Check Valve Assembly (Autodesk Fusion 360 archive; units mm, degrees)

design "Check Valve Assembly" references "PC012-406-7000-SST-0810-C-N-IN", "Bottom End Cap", "Check Valve Upper Body", "Check Valve PTFE Seal", "Check Valve Lower Body", "9559K16_Ultra-Chemical-Resistant Rigid PTFE O-Ring", "Knife Edge Check Valve Poppet"
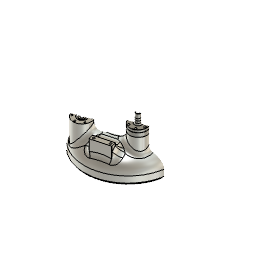
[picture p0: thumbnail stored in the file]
description: Part Number
part number: 9559K61_Ultra-Chemical-Resistant Rigid PTFE O-Ring
component_insert "Component Insert1"
component_insert "Component Insert2"
component_insert "Component Insert4"
base_feature "Base Feature1"
joint "Assemble" alignAngle 0 alignOffsetX 0 alignOffsetY 0 alignOffsetZ 0
position "Position1"
as_built_joint "As-built3"
position "Position2"
as_built_joint "As-built4"
component_insert "Component Insert9"
position "Position3"
as_built_joint "As-built5"
base_feature "Base Feature1"
move_face "MoveFace1"
position "Position4"
as_built_joint "As-built6"
component_insert "Component Insert10"
joint "Assemble" alignAngle 210 alignOffsetX 0 alignOffsetY 0 alignOffsetZ 0
component_insert "Component Insert11"
joint "Assemble" alignAngle 0 alignOffsetX 0 alignOffsetY 0 alignOffsetZ 0
component_insert "Component Insert12"
joint "Assemble" alignAngle 20 alignOffsetX 0 alignOffsetY 0 alignOffsetZ 0
step "GeometricRelationship1" Offset 0
component_insert "Component Insert13"
step "GeometricRelationship2" Offset 0
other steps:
create_component "CreateComponent1"
create_component "CreateComponent2"

design "PC012-406-7000-SST-0810-C-N-IN"
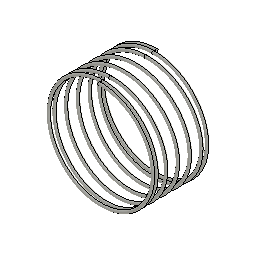
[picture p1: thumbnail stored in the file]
description: Part Number
part number: ANIMATE_PC
base_feature "Base Feature"

design "Bottom End Cap" references "flats for machining"
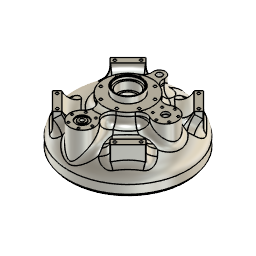
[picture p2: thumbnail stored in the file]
sketch "Sketch1" plane through (0, 0, 0) normal (1, 0, 0) x axis (0, 1, 0)
  line L1 (0, 0) -> (0, 44.45)
  line L2 (88.9, 0) -> (84.455, 0)
  line L3 (88.9, -12.7) -> (88.9, 0)
  line L4 (84.455, -12.7) -> (88.9, -12.7)
  line L5 (84.455, 0) -> (84.455, -12.7)
  curve K1 (0, 40.005) -> (0, -40.005)
  curve K2 (-84.455, 0) -> (84.455, 0)
  curve K3 (88.9, 0) -> (-88.9, 0)
  curve K4 (0, 44.45) -> (0, -44.45)
  line L6 (88.9, 0) -> (0, 0)
  line L7 (0, 44.45) -> (0, 0)
  line L8 (86.5378, -16.0736) -> (88.9, -12.7)
  line L9 (85.471, -16.0736) -> (86.5378, -16.0736)
  line L10 (84.455, -12.7) -> (84.455, -16.0736)
  line L11 (84.455, -16.0736) -> (85.471, -16.0736)
  line L12 (84.963, -16.0736) -> (84.455, -15.5656)
  closed curve K5 centre (0, 0)
  closed curve K6 centre (0, 0)
  point P9 (0, -40.005)
  point P10 (0, 40.005)
  point P11 (84.455, 0)
  point P12 (-84.455, 0)
  point P1 (0, 0)
  point P8 (0, 0)
  point P14 (-88.9, 0)
  point P15 (88.9, 0)
  point P16 (0, -44.45)
  point P17 (0, 44.45)
  point P4 (0, 0)
  point P13 (0, 0)
  point P5 (88.9, 0)
  point P3 (0, 44.45)
  point P18 (0, 0)
  point P19 (0, 0)
  point P20 (0, 44.45)
  point P24 (84.455, -15.5656)
  point P25 (84.963, -16.0736)
  point P2 (84.455, 0)
  point P7 (84.455, -12.7)
  point P6 (88.9, -12.7)
  point P21 (86.5378, -16.0736)
  point P22 (85.471, -16.0736)
  horizontal L2
  vertical L3
  horizontal L4
  vertical L5
  coincident K5 P9
  coincident K5 P10
  coincident K5 P11
  coincident K5 P12
  coincident P1 P8
  coincident K6 P14
  coincident K6 P15
  coincident K6 P16
  coincident K6 P17
  coincident P4 P13
  coincident P5 P15
  perpendicular L3 K3
  coincident P3 P17
  coincident P13 P18
  coincident P1 P19
  coincident P17 P20
  horizontal K2
  coincident P8 P13
  perpendicular L3 L9
  perpendicular L10 L11
  vertical L10
  coincident L10 P24
  coincident L11 P25
  dimension "d10" distance P1 P3 = 44.45
  dimension "d126" distance P2 P7 = 12.7
  dimension "d127" distance P6 P7 = 4.445
  dimension "d282" = 84.455
  dimension "d283" distance K5 = 40.005
  dimension "d284" distance K6 = 88.9
  dimension "d285" = 44.45
  dimension "d347" angle L4 L8 = 55
  dimension "d348" distance P21 P22 = 1.0668
  dimension "d358" distance L3 P21 = 2.3622
  dimension "d449" angle L11 L12 = 45
  dimension "d450" distance L10 P25 = 0.508
work_plane "WorkPlane2" AlongDistance 56.007
sketch "Sketch2" plane through (0, 0, 56.007) normal (0, 0, 1) x axis (1, 0, 0)
  line L1 (-88.9, 0) -> (0, 0)
  line L2 (0, -35.941) -> (0, 0)
  line L3 (0, 46.99) -> (0, 0)
  line L4 (0, -68.6054) -> (0, -35.941)
  line L5 (0, 0) -> (41.1476, -26.1762)
  line L6 (0, 0) -> (56.261, 0)
  line L7 (44.1626, 6.985) -> (56.261, 0)
  line L8 (0, 0) -> (28.6996, -11.8878)
  line L9 (7.5692, -55.4952) -> (0, -68.6054)
  line L10 (-6.35, -51.2658) -> (-6.35, -35.3756)
  line L11 (6.35, -50.7799) -> (6.35, -35.3756)
  line L12 (6.35, -51.2658) -> (6.35, -50.7799)
  circle C1 centre (0, 0) radius 20.32
  circle C2 centre (0, 0) radius 35.941
  circle C3 centre (11.8878, -28.6996) radius 2.032
  circle C4 centre (28.6996, -11.8878) radius 2.032
  circle C5 centre (28.6996, 11.8878) radius 2.032
  circle C6 centre (11.8878, 28.6996) radius 2.032
  circle C7 centre (-11.8878, 28.6996) radius 2.032
  circle C8 centre (-28.6996, 11.8878) radius 2.032
  circle C9 centre (-28.6996, -11.8878) radius 2.032
  circle C10 centre (-11.8878, -28.6996) radius 2.032
  circle C11 centre (0, -68.6054) radius 18.4658
  circle C12 centre (0, -68.6054) radius 3.2004
  circle C13 centre (0, 0) radius 88.9
  circle C14 centre (0, -68.6054) radius 6.0452
  circle C15 centre (0, -68.6054) radius 9.525
  circle C16 centre (56.261, 0) radius 17.399
  circle C17 centre (41.1476, 26.1762) radius 12.827
  circle C18 centre (41.1476, -26.1762) radius 12.827
  circle C19 centre (0, 46.99) radius 8.89
  circle C20 centre (56.261, 0) radius 5.3975
  circle C21 centre (56.261, 0) radius 13.97
  circle C22 centre (56.261, 0) radius 4.7625
  circle C23 centre (0, -68.6054) radius 15.1384
  circle C24 centre (-21.4789, 43.7833) radius 12.827
  circle C25 centre (21.4789, 43.7833) radius 12.827
  circle C26 centre (56.261, 0) radius 10.3632
  circle C27 centre (56.261, 0) radius 7.7978
  point P1 (0, 0)
  point P2 (0, 0)
  point P20 (0, 0)
  point P21 (-88.9, 0)
  point P3 (0, 0)
  point P22 (0, 0)
  point P23 (0, -35.941)
  point P24 (0, 0)
  point P25 (0, 46.99)
  point P26 (0, 46.99)
  point P16 (0, -68.6054)
  point P27 (0, -68.6054)
  point P19 (41.1476, -26.1762)
  point P28 (41.1476, -26.1762)
  point P29 (0, 0)
  point P17 (56.261, 0)
  point P32 (56.261, 0)
  point P33 (0, 0)
  point P31 (56.261, 0)
  point P34 (56.261, 0)
  point P35 (44.1626, 6.985)
  point P36 (44.1626, 6.985)
  point P5 (28.6996, -11.8878)
  point P39 (28.6996, -11.8878)
  point P40 (0, 0)
  point P41 (7.5692, -55.4952)
  point P13 (0, -68.6054)
  point P42 (0, -68.6054)
  point P43 (7.5692, -55.4952)
  point P14 (0, 0)
  point P38 (0, -68.6054)
  point P48 (-6.35, -35.3756)
  point P49 (-6.35, -51.2658)
  point P50 (6.35, -35.3756)
  point P52 (6.35, -51.2658)
  point P4 (11.8878, -28.6996)
  point P30 (56.261, 0)
  coincident P1 P2
  concentric C1 C2
  concentric C11 C12
  concentric C2 C13
  concentric C12 C14
  concentric C12 C15
  tangent C2 C17
  tangent C16 C17
  coincident P2 P20
  coincident C13 P21
  horizontal L1
  coincident P3 P22
  coincident C2 P23
  perpendicular L1 L2
  coincident P1 P24
  coincident P25 P26
  coincident P16 P27
  coincident P19 P28
  coincident P1 P29
  concentric C16 C20
  horizontal P2 P17
  tangent C16 C18
  concentric C16 C21
  coincident P17 P32
  coincident P3 P33
  coincident P31 P34
  coincident C21 P35
  coincident P35 P36
  concentric C20 C22
  concentric C12 C23
  vertical L3
  coincident P5 P39
  coincident P3 P40
  coincident C23 P41
  coincident P13 P42
  coincident P41 P43
  vertical P14 P38
  tangent C19 C24
  tangent C2 C24
  equal C24 C25
  tangent C2 C25
  tangent C19 C25
  concentric C22 C26
  concentric C20 C27
  coincident C2 P48
  coincident C11 P49
  vertical L10
  coincident C2 P50
  coincident C11 P52
  parallel L11 L12
  vertical L11
  tangent C2 C18
  dimension "d16" diameter C1 = 40.64
  dimension "d17" diameter C2 = 71.882
  dimension "d19" distance P3 P4 = 31.0642
  dimension "d20" diameter C3 = 4.064
  dimension "d30" diameter C11 = 36.9316
  dimension "d31" diameter C12 = 6.4008
  dimension "d60" diameter C13 = 177.8
  dimension "d61" distance P13 P14 = 68.6054
  dimension "d111" diameter C14 = 12.0904
  dimension "d112" diameter C15 = 19.05
  dimension "d133" diameter C16 = 34.798
  dimension "d163" diameter C17 = 25.654
  dimension "d250" distance P24 P25 = 46.99
  dimension "d251" diameter C19 = 17.78
  dimension "d276" diameter C18 = 25.654
  dimension "d332" diameter C20 = 10.795
  dimension "d338" angle L6 L7 = 30
  dimension "d341" diameter C21 = 27.94 (= "( 0.55 * 2 ) * 1 in")
  dimension "d342" diameter C22 = 9.525
  dimension "d343" distance P2 P30 = 56.261
  dimension "d359" diameter C23 = 30.2768
  dimension "d360" angle L6 L8 = 22.5
  dimension "d361" angle L4 L9 = 30
  dimension "d370" diameter C24 = 25.654
  dimension "d387" diameter C26 = 20.7264
  dimension "d388" distance C26 C27 = 2.5654
  dimension "d413" distance L4 L10 = 6.35
  dimension "d416" distance L4 L11 = 6.35
  dimension "d22" C-Pattern1-Angle = 360
work_plane "WorkPlane3" AlongDistance 0
revolve "Revolve3" sketch "Sketch1" AlongAngle 360
work_plane "WorkPlane5" AlongDistance 45.3644
sketch "Sketch4" plane through (0, 0, 45.3644) normal (0, 0, 1) x axis (1, 0, 0)
  circle C1 centre (0, 0) radius 12.7
  circle C2 centre (0, 0) radius 15.7099
  circle C3 centre (0, 0) radius 18.288
  circle C4 centre (0, 0) radius 20.32
  point P1 (0, 0)
  point P2 (0, 0)
  point P3 (0, 0)
  coincident P1 P2
  coincident P1 P3
  concentric C1 C3
  concentric C3 C4
  dimension "d79" diameter C1 = 25.4
  dimension "d80" diameter C2 = 31.4198
  dimension "d81" diameter C3 = 36.576
  dimension "d82" diameter C4 = 40.64
extrude "Extrude13" new body sketch "Sketch4" against normal blind 2.0828
extrude "Extrude14" add sketch "Sketch2" profile of C1 C2 C3 C4 C5 C6 C7 C8 C9 C10 L1 L2 L3 L5 to an object
extrude "Extrude15" add sketch "Sketch4" profile of C1 C2 along normal blind 4.0894
extrude "Extrude16" add sketch "Sketch4" profile of C2 C3 along normal blind 15.2654
extrude "Extrude17" add sketch "Sketch4" profile of C3 C4 along normal blind 19.9644
extrude "Extrude19" cut sketch "Sketch4" profile of C1 against normal blind 25.4
hole "Hole1" HoleDepth 10.795 HoleDiameter 4.064 TipAngle 118
circular_pattern "C-Pattern1" TotalAngle 360
extrude "Extrude20" add sketch "Sketch2" profile of C11 C12 C14 C15 L4 to an object
extrude "Extrude21" sketch "Sketch2" profile of C14 C15 blind -1.7018
extrude "Extrude22" cut sketch "Sketch2" profile of C12 against normal blind 50.8
hole "Hole2" HoleDepth 17.78 HoleDiameter 3.429 TipAngle 118
circular_pattern "C-Pattern2" TotalAngle 360
sketch "Sketch5" plane through (0, 0, 45.3644) normal (0, 0, 1) x axis (1, 0, 0)
  line L1 (-70.046, 43.1052) -> (-62.8618, 35.921)
  line L2 (-43.1052, 70.046) -> (-70.046, 43.1052)
  line L3 (-35.921, 62.8618) -> (-43.1052, 70.046)
  line L4 (-62.8618, 35.921) -> (-35.921, 62.8618)
  line L5 (-35.56, 0) -> (0, 0)
  line L6 (-52.9835, 52.9835) -> (0, 0)
  line L7 (-43.1052, 70.046) -> (-62.8618, 35.921)
  line L8 (-35.921, 62.8618) -> (-70.046, 43.1052)
  line L9 (-62.7935, 43.0374) -> (-43.1735, 62.9296)
  circle C1 centre (0, 0) radius 88.9
  point P1 (0, 0)
  point P2 (0, 0)
  point P8 (0, 0)
  point P10 (0, 0)
  point P7 (-52.9835, 52.9835)
  point P11 (-52.9835, 52.9835)
  point P13 (-43.1735, 62.9296)
  point P14 (-43.1735, 62.9296)
  point P12 (-62.7935, 43.0374)
  point P15 (-62.7935, 43.0374)
  point P3 (-62.8618, 35.921)
  point P4 (-70.046, 43.1052)
  point P6 (-35.921, 62.8618)
  coincident P1 P2
  perpendicular L1 L2
  perpendicular L2 L3
  parallel L2 L4
  coincident P1 P8
  horizontal L5
  coincident P2 P10
  coincident P7 P11
  midpoint P7 L7
  perpendicular L4 L6
  coincident P13 P14
  coincident P12 P15
  midpoint P7 L9
  dimension "d138" diameter C1 = 177.8
  dimension "d147" distance P3 P4 = 10.16
  dimension "d148" distance P3 P6 = 38.1
  dimension "d149" distance P2 P7 = 74.93
  dimension "d208" angle L5 L6 = 45
  dimension "d329" distance P12 P13 = 27.94
extrude "Extrude24" add sketch "Sketch5" profile of L1 L2 L3 L4 L6 to an object
hole "Hole5" HoleDepth 19.05 HoleDiameter 4.064 TipAngle 118
circular_pattern "C-Pattern4" TotalAngle 360
circular_pattern "C-Pattern9" TotalAngle 360
extrude "Extrude25" add sketch "Sketch2" profile of C2 C16 C17 C18 to an object
sketch "Sketch7" plane through (0, 0, 0) normal (0, 0, 1) x axis (1, 0, 0)
  line L1 (38.8768, -21.5498) -> (0, 0)
  line L2 (0, -34.3143) -> (0, 0)
  circle C1 centre (38.8768, -21.5498) radius 8.89
  circle C2 centre (38.8768, -21.5498) radius 11.43
  point P1 (0, 0)
  point P2 (0, 0)
  point P4 (0, 0)
  point P3 (38.8768, -21.5498)
  point P6 (38.8768, -21.5498)
  coincident P1 P2
  coincident P1 P4
  vertical L2
  coincident P3 P6
  concentric C1 C2
  dimension "d219" diameter C1 = 17.78
  dimension "d220" distance P2 P3 = 44.45
  dimension "d221" diameter C2 = 22.86
  dimension "d444" angle L1 L2 = 61 (= "90 deg - 29 deg")
extrude "Extrude30" add sketch "Sketch7" profile of C1 C2 to an object from offset 22.098
fillet "Fillet31" radius 11.938
extrude "Extrude29" cut of existing geometry blind -1.27
revolve "Revolve5" sketch "Sketch1" AlongAngle 360
extrude "Extrude32" add sketch "Sketch2" profile of C19 to an object
hole "Hole6" HoleDiameter 7.9502 TipAngle 118
extrude "Extrude41" add sketch "Sketch2" profile of C2 L3 C19 C24 C25 to an object
work_plane "WorkPlane7" AlongDistance 37.846
sketch "Sketch9" plane through (0, 0, 37.846) normal (0, 0, 1) x axis (1, 0, 0)
  line L1 (21.5526, 21.5526) -> (0, 0)
  line L2 (-25.4, 0) -> (0, 0)
  circle C1 centre (21.5526, 21.5526) radius 8.89
  point P1 (0, 0)
  point P2 (0, 0)
  point P3 (21.5526, 21.5526)
  point P4 (21.5526, 21.5526)
  point P5 (0, 0)
  point P6 (-25.4, 0)
  coincident P1 P2
  coincident P3 P4
  coincident P1 P5
  horizontal L2
  dimension "d314" distance P2 P3 = 30.48
  dimension "d315" diameter C1 = 17.78
  dimension "d316" distance P5 P6 = 25.4
  dimension "d317" = 225
fillet "Fillet34" radius 0.508
fillet "Fillet29" radius 16.51
hole "Hole7" HoleDepth 12.7 HoleDiameter 3.429 TipAngle 118
circular_pattern "C-Pattern10" TotalAngle 360
extrude "Extrude37" cut sketch "Sketch2" profile of C22 against normal blind 40.64
extrude "Extrude38" cut sketch "Sketch2" profile of C20 C22 against normal blind 3.175
extrude "Extrude44" add sketch "Sketch7" profile of C1 blind 2.54 from offset 30.48
fillet "Fillet36" EdgeOffset1 12.954 EdgeOffset2 12.7
chamfer "Chamfer1" distance 0.762
extrude "Extrude45" add of existing geometry blind 0.0762
extrude "Extrude46" add of existing geometry to an object
sketch "Sketch10" plane through (0, 0, 0) normal (0, 1, 0) x axis (1, 0, 0)
component_insert "Component Insert"
joint "Assemble3" alignAngle 45 alignOffsetX 0 alignOffsetY 0 alignOffsetZ 0
position "Position2"
ground "Pin"
extrude "Extrude47" add sketch "Sketch2" profile of C2 C11 L4 L10 L11 L12 to an object
fillet "Fillet38" radius 12.954
fillet "Fillet44" radius 12.954
sketch "Sketch11" plane through (58.3717, -58.3717, 0) normal (0.7071, -0.7071, 0) x axis (0.7071, 0.7071, 0)
  line L1 (41.6366, -35.1236) -> (-41.6366, -35.1236)
  line L2 (41.6366, -18.6136) -> (41.6366, -35.1236)
  line L3 (-41.6366, -18.6136) -> (41.6366, -18.6136)
  line L4 (-41.6366, -35.1236) -> (-41.6366, -18.6136)
split_face "SplitFace1"
extrude "Extrude48" cut of existing geometry blind -1.143
extrude "Extrude49" cut of existing geometry blind -1.143
fillet "Fillet45" radius 60.96
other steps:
thread "Thread1" ThreadOffset 0 ThreadDepth 5.9436
thread "Thread2" ThreadOffset 0 ThreadDepth 5.9436
thread "Thread5" ThreadOffset 0 ThreadDepth 5.9436
thread "Thread6" ThreadOffset 0 ThreadDepth 0
thread "Thread7" ThreadOffset 0 ThreadDepth 5.9436
joint_origin "JointOrigin2"

design "Check Valve Upper Body"
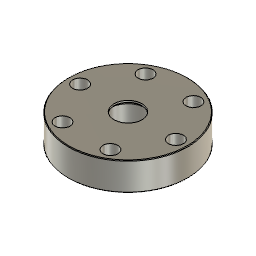
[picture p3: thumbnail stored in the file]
description: Part Number
part number: 9559K114_Ultra-Chemical-Resistant Rigid PTFE O-Ring
sketch "Sketch1" plane through (0, 0, 0) normal (0, 1, 0) x axis (1, 0, 0)
  line L1 (5.1816, -6.5786) -> (5.1816, 0)
  line L2 (30.734, -8.2042) -> (4.064, -8.2042)
  line L3 (17.399, -8.2042) -> (17.399, 0)
  line L4 (17.399, -8.2042) -> (4.064, -8.2042)
  line L5 (5.1816, -6.5786) -> (4.064, -7.6962)
  line L6 (4.064, -7.6962) -> (4.064, -8.2042)
  line L7 (17.399, 0) -> (5.1816, 0)
  line L8 (0, 6.4615) -> (0, -18.5264)
  line L9 (10.3632, 0) -> (0, 0)
  line L10 (10.3632, -1.0668) -> (10.3632, 0)
  line L11 (7.7978, -1.0668) -> (10.3632, -1.0668)
  line L12 (7.7978, 0.0002) -> (7.7978, -1.0668)
  line L13 (5.969, -6.5786) -> (5.1816, -6.5786)
  line L14 (5.969, 0) -> (5.969, -6.5786)
  line L15 (5.1816, 0) -> (5.969, 0)
  point P7 (17.399, -8.2042)
  point P1 (0, 0)
  point P3 (5.1816, -6.5786)
  point P8 (5.1816, -6.5786)
  point P12 (0, 0)
  point P18 (5.969, 0)
  point P4 (4.064, -8.2042)
  point P9 (4.064, -7.6962)
  point P13 (10.3632, 0)
  point P14 (10.3632, -1.0668)
  point P15 (7.7978, -1.0668)
  midpoint L2 P7
  coincident P1 L7
  vertical L8
  coincident P1 L8
  vertical L3
  horizontal L7
  vertical L1
  vertical L6
  coincident P3 P8
  coincident P1 P12
  perpendicular L1 L9
  perpendicular L7 L10
  perpendicular L10 L11
  perpendicular L1 L13
  coincident L9 P18
  perpendicular L9 L14
  dimension "d55" = 10.3632
  dimension "d56" = 34.798
  dimension "d57" distance L4 L7 = 8.2042
  dimension "d58" angle L4 L5 = 45
  dimension "d59" distance P4 P9 = 0.508
  dimension "d60" = 8.128
  dimension "d65" distance P12 P13 = 10.3632
  dimension "d66" distance P13 P14 = 1.0668
  dimension "d67" distance P14 P15 = 2.5654
  dimension "d68" angle L11 L12 = 90
  dimension "d74" = 11.938
  dimension "d53" AlongDistance = -26.67
  dimension "d54" TaperAngle = 0
  dimension "d47" alignAngle = 0
  dimension "d48" alignOffsetX = 0
  dimension "d49" alignOffsetY = 0
  dimension "d50" alignOffsetZ = -1.016
  dimension "d51" distance = -12.7
  dimension "d52" diameter = 30.48
revolve "Revolve1" sketch "Sketch1" AlongAngle 360
sketch "Sketch4" plane through (0, 0, 8.2042) normal (0, 0, 1) x axis (-1, 0, 0)
  line L1 (13.97, 0) -> (0, 0)
  circle C1 centre (0, 0) radius 17.399
  circle C2 centre (0, 0) radius 4.064
  point P2 (0, 0)
  point P3 (0, 0)
  point P4 (13.97, 0)
  coincident P2 P3
  horizontal L1
  dimension "d13" distance P3 P4 = 13.97
hole "Hole1" HoleDiameter 4.318 TipAngle 118
circular_pattern "C-Pattern1" TotalAngle 360
base_feature "Base Feature"
delete_face "DeleteFace1"
revolve "Revolve5" sketch "Sketch1" AlongAngle 360
revolve "Revolve6" sketch "Sketch1" AlongAngle 360
chamfer "Chamfer1" distance 0.1778 distance 0.1778
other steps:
create_component "CreateComponent6"

design "Knife Edge Check Valve Poppet"
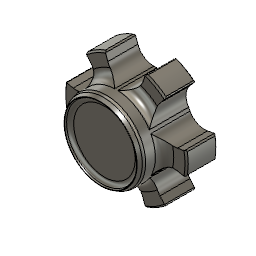
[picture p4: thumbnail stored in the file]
sketch "Sketch1" plane through (0, 0, 0) normal (1, 0, 0) x axis (0, 0, -1)
  line L1 (-19.05, 0) -> (0, 0)
  line L2 (-4.9004, 3.81) -> (-2.9273, 3.81)
  line L3 (-5.3403, 3.556) -> (-4.9004, 3.81)
  line L4 (-2.9274, 5.9563) -> (-2.9273, 3.81)
  line L5 (0, 5.9563) -> (-2.9274, 5.9563)
  line L6 (0, 0) -> (0, 5.9563)
  line L7 (-5.3403, 3.5052) -> (-5.3403, 3.556)
  line L8 (-4.9593, 3.2852) -> (-5.3403, 3.5052)
  line L9 (-4.9593, 0) -> (-4.9593, 3.2852)
  point P1 (0, 0)
  point P2 (0, 0)
  point P9 (0, 0)
  point P12 (-4.9593, 0)
  point P6 (-5.3403, 3.556)
  point P10 (-5.3403, 3.5052)
  coincident P1 P2
  horizontal L1
  parallel L1 L2
  perpendicular L2 L4
  coincident P1 P9
  perpendicular L1 L6
  perpendicular L2 L7
  coincident L1 P12
  perpendicular L1 L9
  dimension "d1" = 7.62
  dimension "d5" angle L2 L3 = 30
  dimension "d6" = 11.9126
  dimension "d7" distance P6 L4 = 2.413 (= "0.11 in - 0.015 in")
  dimension "d8" distance P6 L6 = 5.3403 (= "0.26025 in - 0.03 in - 0.02 in")
  dimension "d21" distance P6 P10 = 0.0508
  dimension "d22" angle L7 L8 = 120
  dimension "d29" distance L7 L9 = 0.381
  dimension "d30" = 7.112
revolve "Revolve1" sketch "Sketch1" AlongAngle 360
chamfer "Chamfer1" distance 0.0762 distance 0.1524
sketch "Sketch2" plane through (0, 0, 0) normal (0, 0, -1) x axis (-1, 0, 0)
  line L1 (0, 6.35) -> (0, 0)
  line L2 (2.2225, 6.35) -> (0, 6.35)
  line L3 (0, 0) -> (2.2225, 6.35)
  line L4 (-2.2225, 6.35) -> (0, 6.35)
  line L5 (0, 0) -> (-2.2225, 6.35)
  line L6 (0, 0) -> (-6.6105, 1.2503)
  line L7 (-6.6105, 1.2503) -> (-5.4993, 3.175)
  line L8 (-4.388, 5.0997) -> (-5.4993, 3.175)
  line L9 (0, 0) -> (-4.388, 5.0997)
  line L10 (0, 0) -> (-4.388, -5.0997)
  line L11 (-4.388, -5.0997) -> (-5.4993, -3.175)
  line L12 (-6.6105, -1.2503) -> (-5.4993, -3.175)
  line L13 (0, 0) -> (-6.6105, -1.2503)
  line L14 (0, 0) -> (2.2225, -6.35)
  line L15 (2.2225, -6.35) -> (0, -6.35)
  line L16 (-2.2225, -6.35) -> (0, -6.35)
  line L17 (0, 0) -> (-2.2225, -6.35)
  line L18 (0, 0) -> (6.6105, -1.2503)
  line L19 (6.6105, -1.2503) -> (5.4993, -3.175)
  line L20 (4.388, -5.0997) -> (5.4993, -3.175)
  line L21 (0, 0) -> (4.388, -5.0997)
  line L22 (0, 0) -> (4.388, 5.0997)
  line L23 (4.388, 5.0997) -> (5.4993, 3.175)
  line L24 (6.6105, 1.2503) -> (5.4993, 3.175)
  line L25 (0, 0) -> (6.6105, 1.2503)
  circle C1 centre (0, 0) radius 3.81
  circle C2 centre (0, 0) radius 5.8801
  point P1 (0, 0)
  point P2 (0, 0)
  point P3 (0, 0)
  point P6 (0, 0)
  point P8 (0, 0)
  point P20 (0, 0)
  point P34 (0, 0)
  point P5 (2.2225, 6.35)
  point P7 (-2.2225, 6.35)
  point P4 (0, 6.35)
  coincident P1 P2
  coincident P1 P3
  vertical L1
  perpendicular L1 L2
  coincident P2 P6
  perpendicular L1 L4
  coincident P2 P8
  equal L2 L4
  coincident P20 P34
  dimension "d10" distance P5 P7 = 4.445
  dimension "d13" distance P3 P4 = 6.35
  dimension "d14" diameter C1 = 7.62
  dimension "d12" C-Pattern1-Angle = 360
extrude "Extrude1" cut sketch "Sketch2" profile of L3 L5 L6 L9 L10 L13 L14 L17 L18 L21 L22 L25 C1 against normal blind 7.112
fillet "Fillet1" radius 1.5875
fillet "Fillet3" radius 0.889
fillet "Fillet4" radius 0.508
fillet "Fillet5" radius 0.508
fillet "Fillet8" radius 0.127

design "9559K16_Ultra-Chemical-Resistant Rigid PTFE O-Ring"
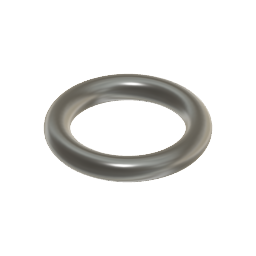
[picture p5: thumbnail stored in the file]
description: Part Number
part number: 9559K16_Ultra-Chemical-Resistant Rigid PTFE O-Ring
base_feature "Base Feature"

design "flats for machining"
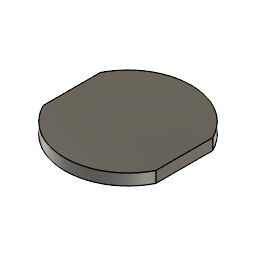
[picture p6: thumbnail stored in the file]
sketch "Sketch1" plane through (0, 0, 0) normal (0, 1, 0) x axis (1, 0, 0)
  line L1 (92.456, 0) -> (0, 0)
  line L2 (92.456, -16.51) -> (92.456, 0)
  line L3 (0, -16.51) -> (92.456, -16.51)
  line L4 (0, 0) -> (0, -16.51)
  line L5 (0, 29.0184) -> (0, -64.1223)
  point P1 (0, 0)
  point P2 (0, 0)
  horizontal L1
  vertical L2
  horizontal L3
  vertical L4
  coincident P1 P2
  vertical L5
  coincident P1 L5
  dimension "d1" distance L1 L3 = 16.51
  dimension "d2" = 184.912
revolve "Revolve1" sketch "Sketch1" AlongAngle 360
sketch "Sketch2" plane through (0, 0, 16.51) normal (0, 0, 1) x axis (-1, 0, 0)
  line L1 (82.55, -264.5608) -> (-82.55, -264.5608)
  line L2 (82.55, 264.5608) -> (82.55, -264.5608)
  line L3 (-82.55, 264.5608) -> (82.55, 264.5608)
  line L4 (-82.55, -264.5608) -> (-82.55, 264.5608)
  line L5 (82.55, 264.5608) -> (-82.55, -264.5608)
  line L6 (-82.55, 264.5608) -> (82.55, -264.5608)
  circle C1 centre (0, 0) radius 92.456
  circle C2 centre (0, 0) radius 88.9
  point P7 (0, 0)
  point P1 (0, 0)
  point P8 (0, 0)
  horizontal L1
  perpendicular L1 L2
  parallel L1 L3
  parallel L2 L4
  coincident L5 P7
  coincident L6 P7
  coincident P1 P7
  coincident P7 P8
  dimension "d4" distance L2 L4 = 165.1
  dimension "d7" diameter C2 = 177.8
extrude "Extrude1" cut sketch "Sketch2" profile of C1 L2 L4 against normal blind 76.2

design "Check Valve PTFE Seal"
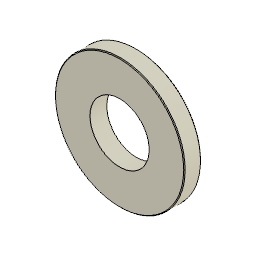
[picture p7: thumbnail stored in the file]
description: Part Number
part number: 96371A203_Abrasion-Resistant ePTFE Plastic Sealing Washer
sketch "Sketch1" plane through (0, 0, 0) normal (0, 0, 1) x axis (1, 0, 0)
  line L1 (0, -2.7861) -> (0, 6.6013)
  line L2 (-6.9596, 0) -> (-4.064, 0)
  line L3 (-6.9596, 1.8136) -> (-6.9596, 0)
  line L4 (-3.175, 1.8136) -> (-6.9596, 1.8136)
  line L5 (-3.175, 0.889) -> (-3.175, 1.8136)
  line L6 (-4.064, 0) -> (-3.175, 0.889)
  line L7 (-3.175, 0) -> (-3.175, 0.889)
  line L8 (-4.064, 0) -> (-3.175, 0)
  point P1 (0, 0)
  vertical L1
  coincident P1 L1
  horizontal L2
  perpendicular L2 L3
  perpendicular L3 L4
  perpendicular L4 L5
  coincident P1 L2
  perpendicular L4 L7
  perpendicular L7 L8
  dimension "d1" angle L4 L6 = 45
  dimension "d2" distance L2 L4 = 1.8136
  dimension "d5" = 8.128
  dimension "d6" = 6.35
  dimension "d7" = 13.9192
revolve "Revolve2" sketch "Sketch1" AlongAngle 360
chamfer "Chamfer2" distance 0.0762
chamfer "Chamfer3" distance 0.0762

design "Check Valve Lower Body"
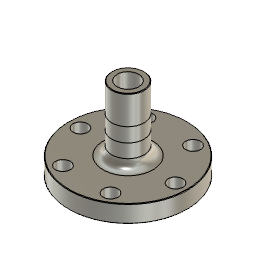
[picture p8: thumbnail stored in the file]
parameter "d65" = 360
parameter "d66" = 1.016
parameter "d95" = 1.651
sketch "Sketch1" plane through (0, 0, 0) normal (0, 1, 0) x axis (1, 0, 0)
  line L1 (17.399, -5.08) -> (17.399, 0)
  line L2 (3.175, -5.08) -> (3.175, -1.778)
  line L3 (17.399, -5.08) -> (4.7625, -5.08)
  line L4 (0, -14.1049) -> (0, 0)
  line L5 (6.985, -1.778) -> (6.985, 0)
  line L6 (6.3881, -1.778) -> (6.985, -1.778)
  line L7 (3.8227, -2.8448) -> (6.3881, -2.8448)
  line L8 (3.8227, -2.8448) -> (3.8227, -1.778)
  line L9 (6.3881, -1.778) -> (6.3881, -2.8448)
  line L10 (3.175, -1.778) -> (3.8227, -1.778)
  line L11 (4.7625, -24.13) -> (4.7625, -5.08)
  line L12 (3.175, -24.13) -> (4.7625, -24.13)
  line L13 (3.175, -5.08) -> (3.175, -24.13)
  line L14 (7.7978, -1.0668) -> (7.7978, 0)
  line L15 (10.3632, -1.0668) -> (7.7978, -1.0668)
  line L16 (10.3632, 0) -> (10.3632, -1.0668)
  line L17 (10.3632, 0) -> (17.399, 0)
  line L18 (6.985, 0) -> (7.7978, 0)
  point P1 (0, 0)
  point P6 (0, 0)
  point P2 (17.399, 0)
  point P3 (17.399, -5.08)
  point P8 (6.985, 0)
  point P9 (6.985, -1.778)
  point P11 (3.8227, -1.778)
  point P12 (3.8227, -2.8448)
  point P13 (6.3881, -2.8448)
  coincident P1 P6
  horizontal L7
  vertical L9
  horizontal L6
  collinear L6 L10
  vertical L8
  horizontal L3
  vertical L5
  coincident P1 L17
  horizontal L17
  vertical L11
  horizontal L12
  vertical L13
  vertical L14
  horizontal L15
  vertical L16
  collinear L17 L18
  dimension "d3" distance P2 P3 = 5.08
  dimension "d64" distance P8 P9 = 1.778
  dimension "d90" distance P11 P12 = 1.0668
  dimension "d94" distance P12 P13 = 2.5654
  dimension "d111" = 7.6454
  dimension "d112" = 6.35
  dimension "d113" = 34.798
  dimension "d114" = 9.525
  dimension "d115" distance L3 L12 = 19.05
  dimension "d116" = 13.97
  dimension "d117" = 20.7264
  dimension "d118" distance L15 L18 = 1.0668
  dimension "d119" distance L14 L16 = 2.5654
  dimension "d23" distance = 9.3853 (= "( 0.739 / 2 ) * 1 in")
  dimension "d24" distance = 1.0668
  dimension "d25" distance = 1.778
  dimension "d26" distance = 1.0668
  dimension "d27" AlongAngle = 360
  dimension "d28" alignAngle = 0
  dimension "d29" alignOffsetX = 0
  dimension "d30" alignOffsetY = 0
  dimension "d31" alignOffsetZ = -2.54
  dimension "d32" alignAngle = 0
  dimension "d33" alignOffsetX = 0
  dimension "d34" alignOffsetY = 0
  dimension "d35" alignOffsetZ = -0.254
  dimension "d36" distance = 4.318
  dimension "d52" distance = 5.08
  dimension "d53" distance = 5.08
  dimension "d54" distance = 3.9751
  dimension "d55" distance = 1.778
  dimension "d56" distance = 0.762
  dimension "d57" angle = 45
  dimension "d58" distance = 0.8128
  dimension "d63" distance = 7.9375
  dimension "d67" alignAngle = 0
  dimension "d68" alignOffsetX = 0
  dimension "d69" alignOffsetY = 0
  dimension "d70" alignOffsetZ = 0.889
  dimension "d74" diameter = 5.08
  dimension "d75" diameter = 6.35
  dimension "d76" AlongDistance = 13.97
  dimension "d77" TaperAngle = 0
  dimension "d78" HoleDepth = 8.636
  dimension "d79" diameter = 5.08
  dimension "d80" TipAngle = 180
  dimension "d89" distance = 3.8227
  dimension "d91" distance = 1.0668
  dimension "d96" distance = 2.5654
  dimension "d97" distance = 2.5654
  dimension "d98" alignAngle = 0
  dimension "d99" alignOffsetX = 0
  dimension "d100" alignOffsetY = 0
  dimension "d101" alignOffsetZ = 0.508
  dimension "d102" HoleDepth = 10.16
  dimension "d103" distance = 15.24
  dimension "d105" diameter = 30.48
  dimension "d106" diameter = 38.1
  dimension "d107" AlongDistance = 12.192
  dimension "d108" TaperAngle = 0
  dimension "d109" AlongDistance = -5.08
  dimension "d110" TaperAngle = 0
revolve "Revolve1" sketch "Sketch1" AlongAngle 360
sketch "Sketch14" plane through (0, 0, 0) normal (0, 0, 1) x axis (1, 0, 0)
  line L1 (0, 0) -> (13.97, 0)
  circle C1 centre (13.97, 0) radius 2.3767
  point P2 (13.97, 0)
  point P3 (13.97, 0)
  point P1 (0, 0)
  point P4 (0, 0)
  coincident P2 P3
  coincident P1 P4
  horizontal L1
  dimension "d120" distance P1 P2 = 13.97
hole "Hole4" HoleDiameter 4.3053 TipAngle 118
circular_pattern "C-Pattern2" TotalAngle 360
chamfer "Chamfer1" distance 0.1524
chamfer "Chamfer2" distance 0.1524
fillet "Fillet1" radius 2.54
work_plane "WorkPlane1" AlongDistance -8.382
work_plane "WorkPlane2" AlongDistance -4.1402
split_face "SplitFace1"
chamfer "Chamfer3" distance 0.127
